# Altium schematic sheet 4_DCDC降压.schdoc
size 309 x 223 mm; Symbol: Sheet-Symbol_A4; Device: Sheet-Symbol_A4; Company: 嘉立创EDA; Version: V1.0; Page Size: A4; @Project Name: 共享电动车中控; @Page Count: 11; @Update Date: 2024-11-20; @Create Date: 2024-09-26; @Schematic Name: SCH; @Page No: 4; @Page Name: DCDC降压; @Board Name: STM32F103C8T6; @Create Time: 02:39:01; @Update Time: 15:12:58
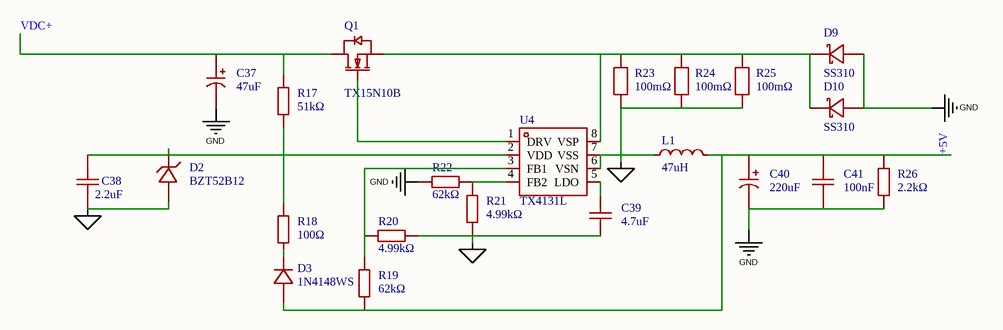
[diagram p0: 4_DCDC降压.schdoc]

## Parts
C37  47uF  [CAP-SMD_BD10.0-L10.3-W10.3-LS11.3-FD]  (value not drawn)
C38  2.2uF  [C0805]  (value not drawn)
C39  4.7uF  [C0805]  (value not drawn)
C40  220uF  [CAP-SMD_BD6.3-L6.6-W6.6-FD]  (value not drawn)
C41  100nF  [C0805]  (value not drawn)
D2  BZT52B12  [SOD-123_L2.7-W1.6-LS3.7-RD]  (value not drawn)
D3  1N4148WS  [SOD-323_L1.8-W1.3-LS2.5-RD]  (value not drawn)
D9  SS310  [SMA_L4.3-W2.6-LS5.0-FD]  (value not drawn)
D10  SS310  [SMA_L4.3-W2.6-LS5.0-FD]  (value not drawn)
L1  47uH  [IND-SMD_L7.0-W6.6_FXL0630]  (value not drawn)
Q1  TX15N10B  [TO-252_L6.5-W6.1-P4.58-LS9.9-BR]  (value not drawn)
R17  51kΩ  [R0805]  (value not drawn)
R18  100Ω  [R0805]  (value not drawn)
R19  62kΩ  [R0603]  (value not drawn)
R20  4.99kΩ  [R0805]  (value not drawn)
R21  4.99kΩ  [R0805]  (value not drawn)
R22  62kΩ  [R0603]  (value not drawn)
R23  100mΩ  [R1206]  (value not drawn)
R24  100mΩ  [R1206]  (value not drawn)
R25  100mΩ  [R1206]  (value not drawn)
R26  2.2kΩ  [R0805]  (value not drawn)
U4  TX4131L  [SOP-8_L4.9-W3.9-P1.27-LS6.0-BL]  (value not drawn)

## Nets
AGND: C38.1 C39.1 D2.2(A) L1.1 R20.2 R21.1 R23.1 R24.1 R25.1 U4.6(VSN) U4.7(VSS)
GND: C37.2 C40.2 C41.1 D9.1(A) D10.1(A) R22.2 R26.1
+5V: C40.1 C41.2 D3.2(A) L1.2 R19.1 R26.2
VDC+: C37.1 Q1.2(D) R17.2
NetC38_2: C38.2 D2.1(K) R17.1 R18.2 U4.2(VDD)
NetC39_2: C39.2 U4.5(LDO)
NetD3_1: D3.1(K) R18.1
NetD9_2: D9.2(K) D10.2(K) Q1.3(S) R23.2 R24.2 R25.2 U4.8(VSP)
NetQ1_1: Q1.1(G) U4.1(DRV)
NetR19_2: R19.2 R20.1 U4.3(FB1)
NetR21_2: R21.2 R22.1 U4.4(FB2)

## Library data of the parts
C37 = RVT2A470M1010_C335988: 容值:47uF;精度:±20%;额定电压:100V;纹波电流:148mA@120Hz;等效串联电阻:-;; Manufacturer: ROQANG(容强); Symbol: VMML1352C470MV; Add into BOM: yes; Tolerance: ±20%; Rated Voltage: 100V; φD: 10mm; L: 10.2mm; Lifetime @ Temp: 2000hrs@105℃
C38 = CL21A225KBQNNNE: 容值:2.2uF;精度:±10%;额定电压:50V;材质(温度系数):X5R;; Manufacturer: SAMSUNG(三星); Add into BOM: yes; Tolerance: ±10%; Voltage Rated: 50V; Temperature Coefficient: X5R
C39 = CL21A475KAQNNNE: 容值:4.7uF;精度:±10%;额定电压:25V;材质(温度系数):X5R;; Manufacturer: SAMSUNG(三星); Symbol: CL10A475KP8NNNC; Add into BOM: yes; Tolerance: ±10%; Voltage Rated: 25V; Temperature Coefficient: X5R
C40 = RVT220UF16V67RV0015: 容值:220uF;精度:±20%;额定电压:16V;纹波电流:110mA@120Hz;等效串联电阻:-;; Manufacturer: KNSCHA(科尼盛); Add into BOM: yes; Tolerance: ±20%; Rated Voltage: 16V; φD: 6.3mm; L: 7.7mm; Lifetime @ Temp: 2000hrs@105℃
C41 = CC0805KRX7R9BB104: 容值:100nF;精度:±10%;额定电压:50V;材质(温度系数):X7R;; Manufacturer: YAGEO(国巨); Symbol: CC0603KRX7R9BB104; Add into BOM: yes; Tolerance: ±10%; Voltage Rated: 50V; Temperature Coefficient: X7R
D2 = BZT52B12_C22395569: 二极管配置:独立式;稳压值(标称值):12V;稳压值(范围):11.76V~12.24V;功率(Pd):500mW;; Manufacturer: 宏迦橙; Symbol: BZT52C12; Add into BOM: yes; Diode Configuration: 独立式; Zener Voltage (Nom): 12V; Reverse Leakage Current (Ir): 100nA@8V; Power Dissipation: 500mW; Zener Impedance (Zzt): 25Ω; Tolerance: ±5%
D3 = 1N4148WS_C2128: 二极管配置:独立式;正向压降(Vf):1.25V@150mA;直流反向耐压(Vr):100V;平均整流电流(Io):150mA;功率:200mW;反向恢复时间(trr):4ns;; Manufacturer: CJ(江苏长电/长晶); Symbol: LS4148PF; Add into BOM: yes; Diode Configuration: 独立式; Reverse Voltage (Vr): 100V; Average Rectified Current (Io): 150mA; Power Dissipation: 200mW; Reverse Leakage Current: 1uA@75V; Reverse Recovery Time (trr): 4ns
D9 D10 = SS310_C7420364: 二极管配置:独立式;正向压降(Vf):850mV@3A;直流反向耐压(Vr):100V;整流电流:3A;; Manufacturer: 宏迦橙; Add into BOM: yes; Diode Configuration: 独立式; Reverse Voltage (Vr): 100V; Rectified Current: 3A; Reverse Leakage Current (Ir): 50uA@100V
L1 = FXL0630-470-M: 电感值:47uH;精度:±20%;额定电流:1.5A;饱和电流(Isat):2A;类型:一体成型电感;; Manufacturer: cjiang(长江微电); Add into BOM: yes; Tolerance: ±20%; Rated Current: 1.5A; Saturation Current (Isat): 2A; DC Resistance (DCR): 385mΩ; Type: 一体成型电感
Q1 = TX15N10B: 类型:1个N沟道;漏源电压(Vdss):100V;连续漏极电流(Id):15A;功率(Pd):34.7W;导通电阻(RDS(on)@Vgs,Id):100mΩ@10V,8A;阈值电压(Vgs(th)@Id):3V@250uA;; Manufacturer: XDS(芯鼎盛); Add into BOM: yes; Type: 1个N沟道; Drain Source Voltage (Vdss): 100V; Continuous Drain Current (Id): 15A; Power Dissipation (Pd): 34.7W
R17 = 0805W8F5102T5E: 电阻类型:厚膜电阻;阻值:51kΩ;精度:±1%;功率:125mW;最大工作电压:150V;温度系数:±100ppm/℃;; Manufacturer: UNI-ROYAL(厚声); Symbol: 0603WAF5102T5E; Add into BOM: yes; Tolerance: ±1%; Power(Watts): 125mW; Overload Voltage (Max): 150V
R18 = 0805W8F1000T5E: 电阻类型:厚膜电阻;阻值:100Ω;精度:±1%;功率:125mW;最大工作电压:150V;温度系数:±100ppm/℃;; Manufacturer: UNI-ROYAL(厚声); Symbol: 0805W8F100LT5E; Add into BOM: yes; Tolerance: ±1%; Power(Watts): 125mW; Overload Voltage (Max): 150V
R19 R22 = 0603WAF6202T5E: 电阻类型:厚膜电阻;阻值:62kΩ;精度:±1%;功率:100mW;最大工作电压:75V;温度系数:±100ppm/℃;; Manufacturer: UNI-ROYAL(厚声); Add into BOM: yes; Tolerance: ±1%; Power(Watts): 100mW; Overload Voltage (Max): 75V
R20 R21 = 0805W8F4991T5E: 电阻类型:厚膜电阻;阻值:4.99kΩ;精度:±1%;功率:125mW;最大工作电压:150V;温度系数:±100ppm/℃;; Manufacturer: UNI-ROYAL(厚声); Symbol: 0603WAF4991T5E; Add into BOM: yes; Tolerance: ±1%; Power(Watts): 125mW; Overload Voltage (Max): 150V
R23-R25 = 1206W4F100LT5E: 电阻类型:厚膜电阻;阻值:100mΩ;精度:±1%;功率:250mW;最大工作电压:200V;温度系数:±800ppm/℃;; Manufacturer: UNI-ROYAL(厚声); Symbol: HOLRS6568-5W-0.1MR-1%; Add into BOM: yes; Tolerance: ±1%; Power(Watts): 250mW; Overload Voltage (Max): 200V; Mounting Sytle: 贴片
R26 = 0805W8F2201T5E: 电阻类型:厚膜电阻;阻值:2.2kΩ;精度:±1%;功率:125mW;最大工作电压:150V;温度系数:±100ppm/℃;; Manufacturer: UNI-ROYAL(厚声); Symbol: 0603WAF2201T5E; Add into BOM: yes; Tolerance: ±1%; Power(Watts): 125mW; Overload Voltage (Max): 150V
U4 = TX4131L_C19192514: Manufacturer: XDS(芯鼎盛); Add into BOM: yes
